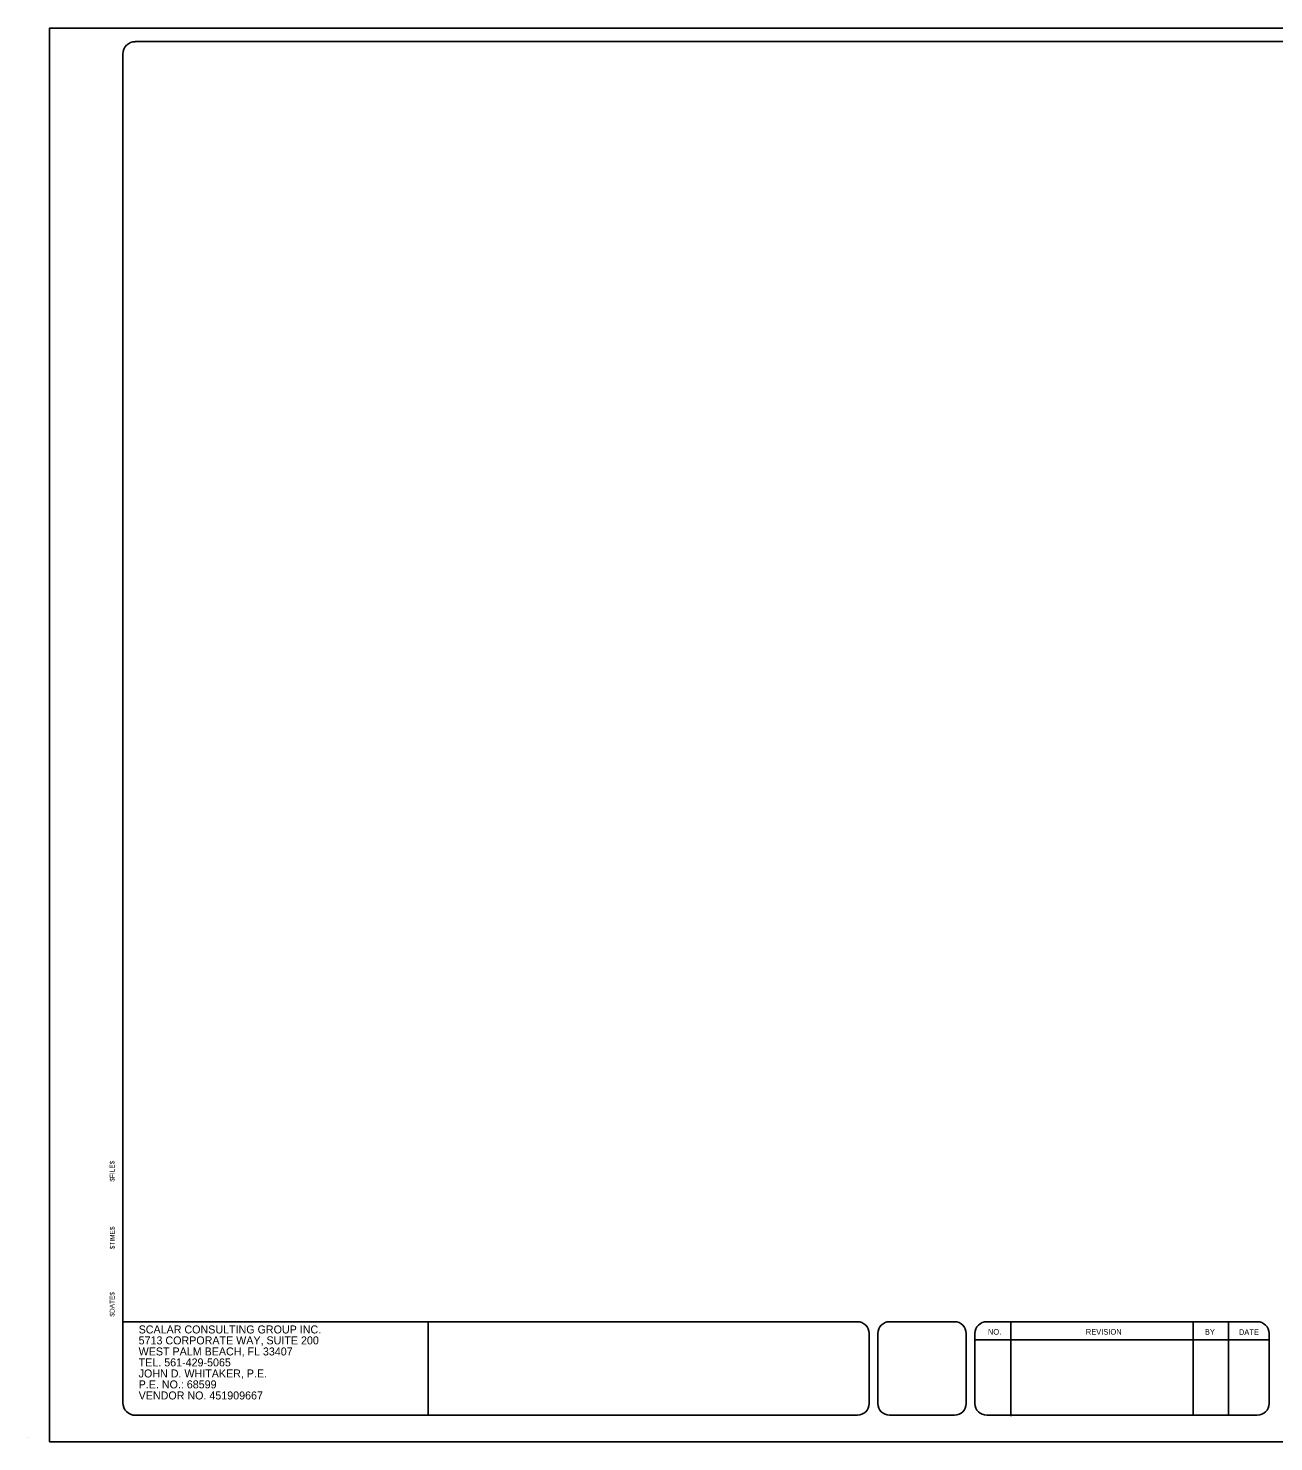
# Model space of a CAD drawing. Extents: x -0.7 to 16, y -0.9 to 9.7.
# Drawn here: x -0.71 to 8.63, y -0.9 to 9.7 of the extents above; entities that cross this region are included whole.
import ezdxf

# ---------------------------------------------------------------- set-up
doc = ezdxf.new("R2010")
doc.units = 0
for name, color, linetype in [('AdhocPoint_dp', 7, 'Continuous'), ('Default', 7, 'Continuous'), ('PlotBorder_dp', 7, 'Continuous')]:
    doc.layers.add(name, color=color, linetype=linetype)

msp = doc.modelspace()

# ---------------------------------------------------------------- linework, layer by layer
at = {"layer": 'AdhocPoint_dp'}
msp.add_line((-0.709, -0.87), (-0.709, -0.87), dxfattribs=at)
at = {"layer": 'Default'}
for p, q in [((15.325, 9.6), (0.094, 9.6)), ((0, -0.608), (0, 9.506)), ((5.508, 0), (0, 0)), ((6.236, 0), (5.75, 0)), ((8.507, 0), (6.478, 0)), ((2.289, -0.701), (2.289, 0)), ((5.596, -0.088), (5.596, -0.613)), ((5.662, -0.088), (5.662, -0.613)), ((6.324, -0.088), (6.324, -0.613)), ((6.39, -0.088), (6.39, -0.613)), ((6.658, -0.004), (6.658, -0.709)), ((8.025, -0.004), (8.025, -0.7)), ((8.29, -0.004), (8.29, -0.7)), ((8.595, -0.088), (8.595, -0.613)), ((8.599, -0.136), (6.393, -0.136)), ((5.508, -0.701), (0.093, -0.701)), ((6.236, -0.701), (5.75, -0.701)), ((8.507, -0.701), (6.478, -0.701))]:
    msp.add_line(p, q, dxfattribs=at)
for centre, major_axis, start_param, end_param in [((0.094, 9.506), (0, -0.0935), 3.141593, 4.712389), ((5.508, -0.088), (0, 0.0882), 4.712389, 6.283185), ((5.75, -0.088), (0, 0.0882), 0, 1.570796), ((6.236, -0.088), (0, 0.0882), 4.712389, 6.283185), ((6.478, -0.088), (0, 0.0882), 0, 1.570796), ((8.507, -0.088), (0, 0.0882), 4.712389, 6.283185), ((0.094, -0.608), (0, -0.0935), 4.712389, 6.283185), ((5.508, -0.613), (0, 0.0882), 3.141593, 4.712389), ((5.75, -0.613), (0, -0.0882), 4.712389, 6.283185), ((6.236, -0.613), (0, 0.0882), 3.141593, 4.712389), ((6.478, -0.613), (0, -0.0882), 4.712389, 6.283185), ((8.507, -0.613), (0, 0.0882), 3.141593, 4.712389)]:
    msp.add_ellipse(centre, major_axis=major_axis, ratio=0.999927, start_param=start_param, end_param=end_param, dxfattribs=at)
at = {"layer": 'PlotBorder_dp'}
msp.add_lwpolyline([(-0.55, -0.9), (15.95, -0.9), (15.95, 9.7), (-0.55, 9.7)], close=True, dxfattribs=at)

# ---------------------------------------------------------------- texts
at = {"layer": 'Default'}
for s, p in [('$FILE$', (-0.062, 1.05)), ('$TIME$', (-0.061, 0.543)), ('$DATE$', (-0.062, 0.038))]:
    msp.add_text(s, height=0.0354, rotation=90, dxfattribs=at).set_placement(p)
for s, height, p in [('SCALAR CONSULTING GROUP INC.', 0.06, (0.119, -0.088)), ('NO.', 0.0421, (6.487, -0.097)), ('REVISION', 0.0421, (7.221, -0.097)), ('BY', 0.0421, (8.114, -0.097)), ('DATE', 0.0421, (8.369, -0.099)), ('WEST PALM BEACH, FL 33407', 0.06, (0.119, -0.253)), ('5713 CORPORATE WAY, SUITE 200', 0.06, (0.119, -0.17)), ('TEL. 561-429-5065', 0.06, (0.119, -0.335)), ('JOHN D. WHITAKER, P.E.', 0.06, (0.119, -0.418)), ('VENDOR NO. 451909667', 0.06, (0.119, -0.583)), ('P.E. NO.: 68599', 0.06, (0.119, -0.5))]:
    msp.add_text(s, height=height, dxfattribs=at).set_placement(p)

doc.saveas('drawing.dxf')
